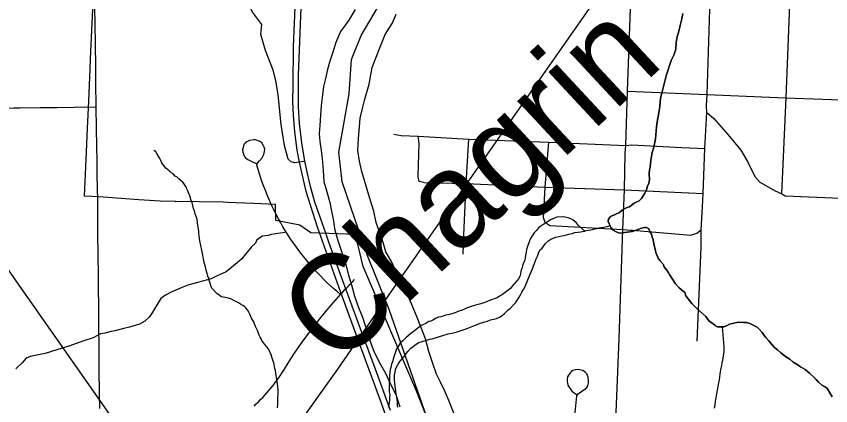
# Model space of a CAD drawing. Extents: x -6.1 to 38, y -7.7 to 22.
# Drawn here: x 4.199 to 5.163, y 17.41 to 17.872 of the extents above; entities that cross this region are included whole.
import ezdxf

# ---------------------------------------------------------------- set-up
doc = ezdxf.new("R2010")
doc.units = 0
for name, color, linetype in [('GM_X_City_Street', 7, 'Continuous'), ('GM_X_Corporation', 7, 'Continuous'), ('GM_X_County_Road', 7, 'Continuous'), ('GM_X_Major_Lake', 7, 'Continuous'), ('GM_X_Major_River', 7, 'Continuous'), ('GM_X_Major_River_Text', 7, 'Continuous'), ('GM_X_Minor_River', 7, 'Continuous'), ('GM_X_Rail_Line', 7, 'Continuous'), ('GM_X_State_Route', 7, 'Continuous'), ('GM_X_Township_Road', 7, 'Continuous'), ('SH_Text', 7, 'Continuous')]:
    doc.layers.add(name, color=color, linetype=linetype)

msp = doc.modelspace()

# ---------------------------------------------------------------- linework, layer by layer
at = {"layer": 'GM_X_City_Street'}
for points in [[(5.10534, 17.66144), (5.11061, 17.7751), (5.11517, 17.89595), (5.11949, 17.98707)], [(4.48963, 17.86204), (4.479, 17.87621), (4.46062, 17.91143), (4.43559, 17.95771)], [(5.01685, 17.77917), (5.01997, 17.88013), (5.02141, 17.89979)], [(4.54082, 17.70012), (4.5342, 17.69885), (4.52825, 17.69818), (4.52464, 17.69927), (4.52108, 17.70258), (4.51665, 17.71853), (4.51266, 17.74333), (4.50911, 17.77877), (4.50646, 17.7956), (4.50336, 17.80778), (4.49428, 17.83126), (4.48852, 17.85008), (4.48963, 17.86204)], [(4.92262, 17.78301), (5.01685, 17.77917), (5.1003, 17.77558), (5.11061, 17.7751), (5.19631, 17.7719)], [(5.00977, 17.60938), (5.00966, 17.61875), (5.01134, 17.64609), (5.01206, 17.66191), (5.01398, 17.71515), (5.01638, 17.75783), (5.01613, 17.76575), (5.01685, 17.77917)], [(5.01638, 17.75783), (5.02477, 17.75064), (5.04131, 17.73169), (5.05666, 17.71299), (5.06481, 17.6998), (5.07321, 17.68182), (5.0792, 17.67534), (5.08639, 17.67102), (5.09671, 17.66527), (5.10534, 17.66144), (5.10917, 17.6588), (5.17464, 17.65616), (5.18663, 17.65592), (5.19214, 17.65808), (5.1923, 17.66455)], [(4.6459, 17.73193), (4.65453, 17.7305), (4.67492, 17.72954), (4.73462, 17.72618), (4.82934, 17.72258), (4.92046, 17.71875), (4.92789, 17.71947), (4.98688, 17.71611), (5.01398, 17.71515)], [(4.68139, 17.67486), (4.67587, 17.67606), (4.67467, 17.68134), (4.67472, 17.68301), (4.67587, 17.72114), (4.67492, 17.72954)], [(4.72815, 17.58974), (4.72905, 17.61229), (4.7315, 17.67342), (4.73462, 17.72618)], [(4.82334, 17.63266), (4.82526, 17.66935), (4.82934, 17.72258)], [(4.68139, 17.67486), (4.7315, 17.67342), (4.82526, 17.66935), (4.91902, 17.66623), (5.01206, 17.66191)], [(4.82334, 17.63266), (4.82478, 17.62786), (4.83078, 17.62379), (4.9171, 17.61923), (4.92649, 17.61843)], [(4.92649, 17.61843), (4.92837, 17.61827), (4.99767, 17.61252), (5.00486, 17.61468), (5.00966, 17.61875)], [(5.0051, 17.48663), (5.0099, 17.59813), (5.00977, 17.60938)]]:
    msp.add_lwpolyline(points, dxfattribs=at)
at = {"layer": 'GM_X_Corporation'}
for points in [[(4.7309, 17.26585), (4.64031, 17.52419), (4.61462, 17.58911), (4.58487, 17.67567), (4.58082, 17.71084), (4.593, 17.77982), (4.59572, 17.8204), (4.60731, 17.8487), (4.63294, 17.8926)], [(4.7309, 17.26585), (4.64031, 17.52419), (4.61462, 17.58911), (4.58487, 17.67567), (4.58082, 17.71084), (4.593, 17.77982), (4.59572, 17.8204), (4.60731, 17.8487), (4.63294, 17.8926)], [(4.70812, 17.33806), (4.67325, 17.42685), (4.60969, 17.57523), (4.60054, 17.61312), (4.54776, 17.6151), (4.53485, 17.62428), (4.50624, 17.62983), (4.5058, 17.64861), (4.47996, 17.6498), (4.44923, 17.65118), (4.44384, 17.65148), (4.38735, 17.65242), (4.3874, 17.65227), (4.36951, 17.65272), (4.34425, 17.65441), (4.2968, 17.65787), (4.27985, 17.65852), (4.28178, 17.70184), (4.28343, 17.73868), (4.28489, 17.77125), (4.2866, 17.80958), (4.28712, 17.82126), (4.28901, 17.86355), (4.28976, 17.88024)]]:
    msp.add_lwpolyline(points, dxfattribs=at)
at = {"layer": 'GM_X_County_Road'}
for points in [[(4.9171, 17.61923), (4.91902, 17.66623), (4.91974, 17.70939), (4.92046, 17.71875), (4.92262, 17.78301), (4.92693, 17.90314), (4.93077, 17.99475), (4.93348, 18.09162), (4.93705, 18.18511)], [(4.29791, 17.40721), (4.29771, 17.42365), (4.2974, 17.45472), (4.29715, 17.47973), (4.29689, 17.50475), (4.29669, 17.52739), (4.29648, 17.55003), (4.29628, 17.56795), (4.29608, 17.58586), (4.29581, 17.61692), (4.29566, 17.63493), (4.29551, 17.65293), (4.29504, 17.68399), (4.29479, 17.70077), (4.29454, 17.71754), (4.29403, 17.73909), (4.29359, 17.76444), (4.29322, 17.79287), (4.2931, 17.81446), (4.29297, 17.83605), (4.2924, 17.86452), (4.29183, 17.89298)], [(4.89028, 17.06011), (4.89554, 17.08535), (4.89792, 17.10008), (4.89925, 17.13375), (4.90132, 17.17999), (4.90503, 17.27928), (4.90895, 17.39239), (4.91279, 17.48998), (4.9171, 17.61923)]]:
    msp.add_lwpolyline(points, dxfattribs=at)
at = {"layer": 'GM_X_Major_Lake'}
for points in [[(4.98822, 17.87488), (4.98636, 17.8669), (4.98486, 17.86081), (4.98263, 17.85092), (4.9815, 17.84788), (4.98039, 17.84065), (4.97967, 17.83267), (4.97742, 17.82544), (4.97441, 17.81935), (4.96841, 17.80109), (4.96542, 17.78853), (4.96355, 17.78207), (4.96168, 17.77484), (4.96097, 17.76458), (4.95949, 17.75508), (4.95799, 17.74899), (4.95689, 17.74063), (4.95581, 17.72657), (4.95395, 17.71668), (4.9517, 17.71022), (4.95022, 17.70109), (4.94949, 17.69311), (4.94874, 17.68969), (4.94838, 17.68551), (4.94879, 17.67791), (4.94805, 17.67411), (4.94616, 17.6703), (4.94504, 17.66612), (4.94316, 17.66231), (4.93901, 17.65583), (4.93637, 17.65316), (4.93296, 17.65162), (4.93031, 17.65047), (4.92502, 17.64588), (4.92236, 17.64511), (4.91972, 17.64395), (4.91631, 17.64203), (4.91329, 17.63936), (4.90798, 17.63667), (4.90268, 17.63436)], [(4.90268, 17.63436), (4.90004, 17.63131), (4.89967, 17.62865), (4.90082, 17.62562), (4.90198, 17.62331)], [(4.90198, 17.62331), (4.90311, 17.62107), (4.90578, 17.61843), (4.9092, 17.61617), (4.913, 17.61467), (4.91907, 17.61546), (4.92855, 17.61665), (4.93915, 17.62051), (4.94256, 17.62129), (4.94522, 17.6213), (4.94788, 17.6198), (4.94903, 17.61676), (4.95094, 17.61374), (4.95171, 17.60994), (4.95286, 17.60729), (4.95364, 17.60198), (4.95441, 17.59856), (4.95557, 17.59439), (4.95634, 17.59174), (4.95902, 17.58529), (4.96093, 17.58226), (4.96511, 17.57773), (4.96551, 17.57507), (4.96779, 17.57243), (4.97084, 17.56865), (4.97237, 17.56562), (4.97581, 17.56032), (4.97962, 17.55464), (4.98381, 17.55011), (4.99066, 17.54445), (4.99182, 17.54065), (4.99868, 17.53158), (5.00439, 17.52591), (5.01543, 17.51609), (5.01925, 17.51042), (5.02343, 17.50778), (5.02647, 17.50552), (5.02914, 17.50364), (5.03672, 17.50368), (5.03975, 17.50483), (5.04354, 17.50675), (5.04695, 17.50791), (5.05377, 17.50947), (5.05984, 17.50874), (5.06364, 17.50876), (5.06743, 17.50764), (5.07313, 17.50502), (5.07618, 17.50351), (5.07846, 17.50087), (5.08189, 17.49709), (5.08456, 17.49368), (5.08647, 17.49104), (5.08951, 17.48763), (5.09371, 17.48234), (5.09675, 17.47932), (5.10018, 17.47668), (5.10399, 17.4729), (5.10969, 17.46875), (5.11464, 17.46536), (5.11882, 17.46197), (5.12339, 17.45933), (5.12757, 17.45632), (5.13289, 17.45331), (5.13822, 17.44878), (5.14317, 17.44425), (5.14584, 17.44122), (5.14888, 17.4382), (5.15269, 17.4348), (5.15649, 17.43254), (5.15954, 17.43029), (5.16489, 17.42082)]]:
    msp.add_lwpolyline(points, dxfattribs=at)
at = {"layer": 'GM_X_Major_River'}
for points in [[(4.60036, 17.87985), (4.59283, 17.86695), (4.58302, 17.85366), (4.57738, 17.84039), (4.57362, 17.82787), (4.57024, 17.81839), (4.56761, 17.80853), (4.56499, 17.79792), (4.56274, 17.78844), (4.56163, 17.77858), (4.56014, 17.76607), (4.55903, 17.75432), (4.5583, 17.74219), (4.55756, 17.73271), (4.55834, 17.72324), (4.55987, 17.71263), (4.56103, 17.70316), (4.56219, 17.68914), (4.56335, 17.67588), (4.56754, 17.6611), (4.57021, 17.65088), (4.57212, 17.64065), (4.57403, 17.63118), (4.57633, 17.61829), (4.58014, 17.60504), (4.58394, 17.59292), (4.58889, 17.5789), (4.59232, 17.56489), (4.59574, 17.55353), (4.59955, 17.54027), (4.60412, 17.52663), (4.60906, 17.51527)], [(4.61155, 17.77337), (4.61691, 17.79125), (4.62056, 17.81099), (4.62428, 17.82126), (4.63023, 17.83609), (4.63581, 17.85015), (4.64405, 17.8631), (4.64889, 17.87413)], [(4.90268, 17.63436), (4.90798, 17.63667), (4.91329, 17.63936), (4.91631, 17.64203), (4.91972, 17.64395), (4.92236, 17.64511), (4.92502, 17.64588), (4.93031, 17.65047), (4.93296, 17.65162), (4.93637, 17.65316), (4.93901, 17.65583), (4.94316, 17.66231), (4.94504, 17.66612), (4.94616, 17.6703), (4.94805, 17.67411), (4.94879, 17.67791), (4.94838, 17.68551), (4.94874, 17.68969), (4.94949, 17.69311), (4.95022, 17.70109), (4.9517, 17.71022), (4.95395, 17.71668), (4.95581, 17.72657), (4.95689, 17.74063), (4.95799, 17.74899), (4.95949, 17.75508), (4.96097, 17.76458), (4.96168, 17.77484), (4.96355, 17.78207), (4.96542, 17.78853), (4.96841, 17.80109), (4.97441, 17.81935), (4.97742, 17.82544), (4.97967, 17.83267), (4.98039, 17.84065), (4.9815, 17.84788), (4.98263, 17.85092), (4.98486, 17.86081), (4.98636, 17.8669), (4.98822, 17.87488)], [(4.60832, 17.68771), (4.60527, 17.70021), (4.60335, 17.71272), (4.60408, 17.72674), (4.60557, 17.74077), (4.6063, 17.751), (4.6093, 17.76389), (4.61155, 17.77337)], [(4.71821, 17.3987), (4.71128, 17.41648), (4.7063, 17.42744), (4.70169, 17.43727), (4.69671, 17.44785), (4.69208, 17.46033), (4.68745, 17.47471), (4.68357, 17.48948), (4.6778, 17.50385), (4.6728, 17.51671), (4.66704, 17.53108), (4.66243, 17.54091), (4.65514, 17.55678), (4.64825, 17.56963), (4.64364, 17.58022), (4.63675, 17.59268), (4.63328, 17.60366), (4.62518, 17.62749), (4.62244, 17.64075), (4.61743, 17.65588), (4.60832, 17.68771)], [(4.87225, 17.61725), (4.86436, 17.62438), (4.86177, 17.62747), (4.85842, 17.63019), (4.85542, 17.63176), (4.85241, 17.63296), (4.84902, 17.63378), (4.84562, 17.63422), (4.8388, 17.63359), (4.83536, 17.63213), (4.83231, 17.63105), (4.82924, 17.62883), (4.82618, 17.62699), (4.8235, 17.62552), (4.82004, 17.62293), (4.81736, 17.62108), (4.81503, 17.61808), (4.81194, 17.6151), (4.80961, 17.61173), (4.80765, 17.60835), (4.80646, 17.60571), (4.80406, 17.59892), (4.80324, 17.59552), (4.80279, 17.59211), (4.80197, 17.58871), (4.80153, 17.5853), (4.8007, 17.5819), (4.79912, 17.57851), (4.79832, 17.57587), (4.7975, 17.57284), (4.79631, 17.56983), (4.79586, 17.56642), (4.79505, 17.5634), (4.79348, 17.56077), (4.79154, 17.55815), (4.78883, 17.55516), (4.78611, 17.55179), (4.78417, 17.54917), (4.78149, 17.54732), (4.77457, 17.54213), (4.77113, 17.5403), (4.76844, 17.53807), (4.75929, 17.53482), (4.75586, 17.53337), (4.75243, 17.53229), (4.74899, 17.53084), (4.74595, 17.53013), (4.74253, 17.52944), (4.73987, 17.52873), (4.73644, 17.52765), (4.733, 17.5262), (4.73033, 17.52511), (4.7269, 17.52365), (4.72308, 17.5222), (4.72004, 17.52112), (4.71736, 17.52003), (4.71051, 17.51788), (4.7071, 17.51756), (4.70443, 17.51647), (4.70176, 17.51576), (4.69872, 17.51506), (4.69605, 17.51397), (4.69298, 17.51213), (4.68993, 17.51067), (4.68726, 17.50996), (4.68381, 17.50774), (4.68114, 17.50665), (4.67847, 17.50518), (4.67232, 17.50074), (4.66886, 17.49777), (4.66617, 17.49592), (4.66309, 17.49332), (4.6604, 17.49071), (4.65654, 17.48736), (4.65346, 17.48438), (4.65111, 17.48063), (4.64916, 17.47763), (4.64836, 17.47498), (4.64596, 17.46819), (4.64432, 17.46215), (4.64314, 17.45952), (4.64231, 17.45573), (4.64188, 17.45308), (4.64099, 17.44626)], [(4.90198, 17.62331), (4.90082, 17.62562), (4.89967, 17.62865), (4.90004, 17.63131), (4.90268, 17.63436)], [(4.90198, 17.62331), (4.90068, 17.62295), (4.89801, 17.62224), (4.89459, 17.62154), (4.89156, 17.62122), (4.88851, 17.62052), (4.88585, 17.61981), (4.88243, 17.61911), (4.87939, 17.61841), (4.87598, 17.61809), (4.87331, 17.61738), (4.87225, 17.61725)], [(5.16489, 17.42082), (5.15954, 17.43029), (5.15649, 17.43254), (5.15269, 17.4348), (5.14888, 17.4382), (5.14584, 17.44122), (5.14317, 17.44425), (5.13822, 17.44878), (5.13289, 17.45331), (5.12757, 17.45632), (5.12339, 17.45933), (5.11882, 17.46197), (5.11464, 17.46536), (5.10969, 17.46875), (5.10399, 17.4729), (5.10018, 17.47668), (5.09675, 17.47932), (5.09371, 17.48234), (5.08951, 17.48763), (5.08647, 17.49104), (5.08456, 17.49368), (5.08189, 17.49709), (5.07846, 17.50087), (5.07618, 17.50351), (5.07313, 17.50502), (5.06743, 17.50764), (5.06364, 17.50876), (5.05984, 17.50874), (5.05377, 17.50947), (5.04695, 17.50791), (5.04354, 17.50675), (5.03975, 17.50483), (5.03672, 17.50368), (5.02914, 17.50364), (5.02647, 17.50552), (5.02343, 17.50778), (5.01925, 17.51042), (5.01543, 17.51609), (5.00439, 17.52591), (4.99868, 17.53158), (4.99182, 17.54065), (4.99066, 17.54445), (4.98381, 17.55011), (4.97962, 17.55464), (4.97581, 17.56032), (4.97237, 17.56562), (4.97084, 17.56865), (4.96779, 17.57243), (4.96551, 17.57507), (4.96511, 17.57773), (4.96093, 17.58226), (4.95902, 17.58529), (4.95634, 17.59174), (4.95557, 17.59439), (4.95441, 17.59856), (4.95364, 17.60198), (4.95286, 17.60729), (4.95171, 17.60994), (4.95094, 17.61374), (4.94903, 17.61676), (4.94788, 17.6198), (4.94522, 17.6213), (4.94256, 17.62129), (4.93915, 17.62051), (4.92855, 17.61665), (4.91907, 17.61546), (4.913, 17.61467), (4.9092, 17.61617), (4.90578, 17.61843), (4.90311, 17.62107), (4.90198, 17.62331)], [(4.65086, 17.40849), (4.65054, 17.41154), (4.65023, 17.41496), (4.6499, 17.41762), (4.64958, 17.42067), (4.64889, 17.4241), (4.6482, 17.42753), (4.64789, 17.43095), (4.64756, 17.43362), (4.64693, 17.44046), (4.64698, 17.44312), (4.64667, 17.44654), (4.6475, 17.44994), (4.64794, 17.45335), (4.64952, 17.45674), (4.65109, 17.45975), (4.65304, 17.46275), (4.65575, 17.46574), (4.65846, 17.4691), (4.66079, 17.4721), (4.66312, 17.47509), (4.66622, 17.47845), (4.66891, 17.48068), (4.67236, 17.48327), (4.67581, 17.48511), (4.67848, 17.4862), (4.6819, 17.48727), (4.68495, 17.48798), (4.68875, 17.48905), (4.69142, 17.48976), (4.70513, 17.49406), (4.70779, 17.49477), (4.71046, 17.49548), (4.71463, 17.49616), (4.71806, 17.49724), (4.7211, 17.49794), (4.72796, 17.50009), (4.73063, 17.50118), (4.73368, 17.50226), (4.74169, 17.50553), (4.74474, 17.50661), (4.74741, 17.5077), (4.75084, 17.50878), (4.75351, 17.50987), (4.75693, 17.51056), (4.76037, 17.51202), (4.76454, 17.5127), (4.76759, 17.51379), (4.77103, 17.51524), (4.77409, 17.51708), (4.77717, 17.51968), (4.78103, 17.52341), (4.78411, 17.52601), (4.7872, 17.52937), (4.78991, 17.53236), (4.79224, 17.53573), (4.7942, 17.53911), (4.79614, 17.54173), (4.79772, 17.54474), (4.79967, 17.54812), (4.80124, 17.55075), (4.80243, 17.55339), (4.80481, 17.55942), (4.80722, 17.56621), (4.80879, 17.5696), (4.80999, 17.57261), (4.81119, 17.57601), (4.81238, 17.57864), (4.81318, 17.58129), (4.81438, 17.5843), (4.81596, 17.58769), (4.81716, 17.59108), (4.81874, 17.59447), (4.82144, 17.59708), (4.82376, 17.59969), (4.82571, 17.60269), (4.82841, 17.6053), (4.83186, 17.60752), (4.83454, 17.60899), (4.83797, 17.61006), (4.84481, 17.61145), (4.84747, 17.61217), (4.85051, 17.61287), (4.85318, 17.61358), (4.85697, 17.61427), (4.8604, 17.61534), (4.86382, 17.61604), (4.86724, 17.61635), (4.87066, 17.61705), (4.87225, 17.61725)], [(4.60906, 17.51527), (4.61893, 17.4845), (4.62279, 17.4739), (4.63007, 17.45916), (4.63618, 17.44897), (4.64195, 17.43573), (4.64846, 17.42364), (4.65309, 17.40889)], [(4.64099, 17.44626), (4.64092, 17.44285), (4.64086, 17.43944), (4.64043, 17.43678), (4.64031, 17.43071), (4.64062, 17.42691), (4.64131, 17.42348), (4.64086, 17.42007), (4.6408, 17.41665), (4.64037, 17.414), (4.63993, 17.41097), (4.6395, 17.40832)]]:
    msp.add_lwpolyline(points, dxfattribs=at)
at = {"layer": 'GM_X_Minor_River'}
for points in [[(4.42728, 17.55882), (4.42686, 17.56109), (4.42605, 17.56374), (4.42523, 17.56715), (4.42402, 17.57093), (4.42319, 17.57472), (4.42158, 17.58001), (4.42075, 17.5838), (4.4199, 17.58873), (4.41866, 17.59441), (4.41742, 17.60009), (4.41656, 17.60578), (4.4157, 17.61109), (4.41523, 17.61602), (4.41478, 17.6202), (4.41395, 17.62398), (4.41351, 17.6274), (4.41306, 17.63119), (4.41186, 17.63459), (4.41105, 17.63762), (4.41023, 17.64103), (4.40904, 17.64405), (4.40822, 17.64746), (4.4074, 17.65048), (4.4066, 17.65275), (4.40581, 17.65464), (4.40539, 17.65653), (4.40459, 17.6588), (4.4034, 17.66182), (4.40181, 17.66559), (4.40063, 17.66785), (4.39983, 17.67012), (4.39827, 17.67237), (4.39633, 17.675), (4.3944, 17.67687), (4.39208, 17.67873), (4.38938, 17.68096), (4.38708, 17.68244), (4.38475, 17.68506), (4.38207, 17.68653), (4.38013, 17.6884), (4.37628, 17.69175), (4.37238, 17.69701), (4.37121, 17.69889), (4.37004, 17.70077), (4.36886, 17.70303), (4.36768, 17.70529), (4.36572, 17.70829), (4.36416, 17.71093), (4.36261, 17.71242), (4.36222, 17.71317)], [(4.51687, 17.61564), (4.51196, 17.61487), (4.5063, 17.61409), (4.50139, 17.61331), (4.49724, 17.61215), (4.49044, 17.61137), (4.48404, 17.60679), (4.48217, 17.60299), (4.47766, 17.59843), (4.47428, 17.59462), (4.47052, 17.59006), (4.46601, 17.58435), (4.46075, 17.57941), (4.45209, 17.57255), (4.44757, 17.56874), (4.43702, 17.56415), (4.42986, 17.56071), (4.42533, 17.55955), (4.41363, 17.55647), (4.40948, 17.55531), (4.40231, 17.55301), (4.39439, 17.54995), (4.38798, 17.54727), (4.38232, 17.54497), (4.37592, 17.54115), (4.37027, 17.53734), (4.36277, 17.52518), (4.36015, 17.52024), (4.3564, 17.5153), (4.35113, 17.51035), (4.3451, 17.50692), (4.33303, 17.50345), (4.32624, 17.50191), (4.31567, 17.49921), (4.31152, 17.49844), (4.30397, 17.49613), (4.29868, 17.49535), (4.29454, 17.49306), (4.29002, 17.49077), (4.28021, 17.48769), (4.27116, 17.48425), (4.26135, 17.4808), (4.2572, 17.47964), (4.24814, 17.47695), (4.23947, 17.47426), (4.23343, 17.47234), (4.22362, 17.4704), (4.21569, 17.46848), (4.21079, 17.46656), (4.2059, 17.46124), (4.19876, 17.454)], [(4.50822, 17.4078), (4.50854, 17.41161), (4.50883, 17.41617), (4.50876, 17.42036), (4.50906, 17.42454), (4.50898, 17.42911), (4.50891, 17.43291), (4.50847, 17.43632), (4.50804, 17.43897), (4.50762, 17.44163), (4.5072, 17.4439), (4.50678, 17.44618), (4.50635, 17.44883), (4.50591, 17.45224), (4.50511, 17.45451), (4.50468, 17.45679), (4.50427, 17.45906), (4.50385, 17.46095), (4.50305, 17.46322), (4.50225, 17.46549), (4.50145, 17.46775), (4.50103, 17.47003), (4.50023, 17.47229), (4.49904, 17.47532), (4.49708, 17.47832), (4.49359, 17.48244), (4.49165, 17.48469), (4.4897, 17.4877), (4.48891, 17.48958), (4.48773, 17.49146), (4.48655, 17.4941), (4.48575, 17.49637), (4.48495, 17.49864), (4.48337, 17.50165), (4.48218, 17.50429), (4.48099, 17.50731), (4.48019, 17.50958), (4.47863, 17.51221), (4.47745, 17.51409), (4.47666, 17.51598), (4.47547, 17.51862), (4.47429, 17.52126), (4.47272, 17.5239), (4.47078, 17.52614), (4.46923, 17.52801), (4.46731, 17.52912), (4.46462, 17.53059), (4.46232, 17.53207), (4.45925, 17.53392), (4.45733, 17.53465), (4.45388, 17.53648), (4.45159, 17.5372), (4.44853, 17.53829), (4.44625, 17.53863), (4.44396, 17.53897), (4.44168, 17.53931), (4.43898, 17.54154), (4.43705, 17.54303), (4.43048, 17.54975), (4.42929, 17.55239), (4.42888, 17.55429), (4.42808, 17.55655), (4.42728, 17.55882)], [(5.03463, 17.50367), (5.03675, 17.48004), (5.03679, 17.47776), (5.03647, 17.47471), (5.03581, 17.46937), (5.03547, 17.46671), (5.03513, 17.4648), (5.03444, 17.46098), (5.03373, 17.45793), (5.03303, 17.45487), (5.03268, 17.45297), (5.03234, 17.45068), (5.03202, 17.44763), (5.03169, 17.44458), (5.031, 17.44115), (5.0303, 17.43733), (5.02962, 17.43314), (5.02893, 17.42894), (5.02788, 17.42436), (5.02719, 17.42017), (5.02652, 17.41521), (5.02583, 17.4114), (5.02514, 17.40758)]]:
    msp.add_lwpolyline(points, dxfattribs=at)
at = {"layer": 'GM_X_Rail_Line'}
msp.add_lwpolyline([(4.164, 17.08105), (4.22288, 17.11422), (4.28514, 17.16362), (4.3773, 17.2385), (4.46626, 17.31066), (4.52352, 17.37506), (4.57967, 17.45347), (4.643, 17.54537), (5.03778, 18.11028), (5.18813, 18.32179), (5.2285, 18.37664), (5.2671, 18.40903), (5.31379, 18.44323), (5.44065, 18.5342), (5.77322, 18.77518), (5.85708, 18.83753), (5.92575, 18.89871), (5.97472, 18.97128), (6.00159, 19.04095), (6.01392, 19.09362), (6.04108, 19.2873)], dxfattribs=at)
at = {"layer": 'GM_X_State_Route'}
msp.add_line((4.56925, 17.60421), (4.56591, 17.61368), dxfattribs=at)
for points in [[(4.54082, 17.70012), (4.53713, 17.7219), (4.53452, 17.74448), (4.53322, 17.76424), (4.53322, 17.80246), (4.53455, 17.83208), (4.54023, 17.98299)], [(4.64331, 17.37901), (4.63167, 17.41214), (4.61139, 17.46805), (4.59684, 17.50778), (4.58316, 17.54426), (4.56557, 17.59421), (4.55558, 17.62179), (4.54212, 17.66413), (4.5342, 17.69885), (4.5317, 17.71322), (4.52887, 17.73471), (4.52735, 17.75447), (4.52648, 17.77076), (4.5267, 17.78987), (4.52735, 17.83569), (4.53299, 17.97488)], [(4.54513, 17.68012), (4.54473, 17.68194), (4.54082, 17.70012)], [(4.56591, 17.61368), (4.55254, 17.65154), (4.54739, 17.67013), (4.54513, 17.68012)], [(4.64201, 17.40485), (4.62572, 17.44915), (4.60655, 17.50155), (4.5786, 17.57771), (4.56925, 17.60421)]]:
    msp.add_lwpolyline(points, dxfattribs=at)
at = {"layer": 'GM_X_Township_Road'}
for points in [[(3.99071, 17.76057), (4.02177, 17.76106), (4.0413, 17.76137), (4.06083, 17.76168), (4.09177, 17.76192), (4.12269, 17.76216), (4.14392, 17.76242), (4.16514, 17.76269), (4.19621, 17.76308), (4.20323, 17.76316)], [(4.20323, 17.76316), (4.22728, 17.76346), (4.24737, 17.76371), (4.26746, 17.76397), (4.29359, 17.76444)], [(4.58287, 17.54203), (4.5788, 17.54545), (4.57481, 17.54893), (4.57089, 17.55249), (4.56705, 17.5561), (4.56326, 17.55978), (4.55832, 17.56503), (4.5527, 17.57097), (4.54757, 17.57682), (4.54102, 17.58458), (4.53467, 17.59268), (4.52881, 17.60082), (4.52427, 17.6074), (4.51944, 17.61491), (4.51468, 17.62231), (4.51207, 17.62689), (4.50952, 17.63153), (4.50701, 17.63622), (4.50464, 17.64093), (4.50232, 17.64569), (4.5001, 17.6505), (4.49797, 17.65534), (4.49594, 17.66022), (4.49395, 17.66514), (4.49205, 17.67008), (4.49026, 17.67505), (4.48855, 17.68006), (4.48694, 17.68509), (4.48543, 17.69017), (4.48396, 17.69526), (4.48447, 17.69761), (4.48687, 17.70029), (4.49001, 17.7038), (4.49223, 17.70786), (4.49306, 17.71128), (4.49315, 17.71405), (4.49269, 17.71664), (4.4913, 17.71913), (4.48964, 17.72172), (4.48742, 17.72328), (4.48484, 17.72448), (4.48234, 17.72532), (4.48031, 17.72541), (4.47533, 17.72467), (4.47218, 17.72301), (4.47015, 17.72153), (4.46858, 17.71959), (4.46756, 17.71626), (4.46692, 17.7135), (4.46738, 17.71073), (4.46793, 17.70814), (4.46914, 17.70574), (4.47043, 17.70398), (4.47301, 17.70186), (4.47541, 17.70075), (4.47892, 17.69909), (4.48317, 17.69742)], [(4.48056, 17.40997), (4.48321, 17.41247), (4.48581, 17.415), (4.48837, 17.4176), (4.49089, 17.42023), (4.49335, 17.4229), (4.49577, 17.42561), (4.49814, 17.42837), (4.50047, 17.43117), (4.50274, 17.43401), (4.50497, 17.43689), (4.50715, 17.4398), (4.50928, 17.44276), (4.51132, 17.44574), (4.51336, 17.44878), (4.51654, 17.45373), (4.52204, 17.46256), (4.52773, 17.47129), (4.53361, 17.47992), (4.53958, 17.48844), (4.54575, 17.49686), (4.552, 17.50516), (4.55845, 17.51337), (4.565, 17.52144), (4.57172, 17.52941), (4.58287, 17.54203), (4.58467, 17.544), (4.58642, 17.54595), (4.58818, 17.54782), (4.58998, 17.54976), (4.59188, 17.55176), (4.59377, 17.55374), (4.59557, 17.55559), (4.59742, 17.5575), (4.59958, 17.55971)], [(4.85954, 17.39065), (4.86213, 17.41809), (4.86276, 17.42195), (4.86411, 17.42437), (4.86626, 17.42617), (4.86931, 17.42788), (4.87255, 17.4303), (4.87434, 17.432), (4.87569, 17.43407), (4.87649, 17.43703), (4.87659, 17.4391), (4.87613, 17.44413), (4.87542, 17.44601), (4.87434, 17.44799), (4.87272, 17.44978), (4.87129, 17.45086), (4.86958, 17.45194), (4.86635, 17.45292), (4.86375, 17.45328), (4.86115, 17.45301), (4.858, 17.45194), (4.85621, 17.45077), (4.85495, 17.44951), (4.85279, 17.44673), (4.85172, 17.44458), (4.85136, 17.44197), (4.85127, 17.43937), (4.85163, 17.43694), (4.85217, 17.43488), (4.85334, 17.43255), (4.85459, 17.43057), (4.85683, 17.4277), (4.85953, 17.42554), (4.86285, 17.42312)]]:
    msp.add_lwpolyline(points, dxfattribs=at)
at = {"layer": 'SH_Text'}
msp.add_lwpolyline([(4.05377, 17.76448), (4.89626, 16.56236), (4.05377, 17.09999)], close=True, dxfattribs=at)

# ---------------------------------------------------------------- texts
at = {"layer": 'GM_X_Major_River_Text'}
msp.add_text('Chagrin', height=0.11372, rotation=42.89799, dxfattribs=at).set_placement((4.57763, 17.45279))

doc.saveas('drawing.dxf')
